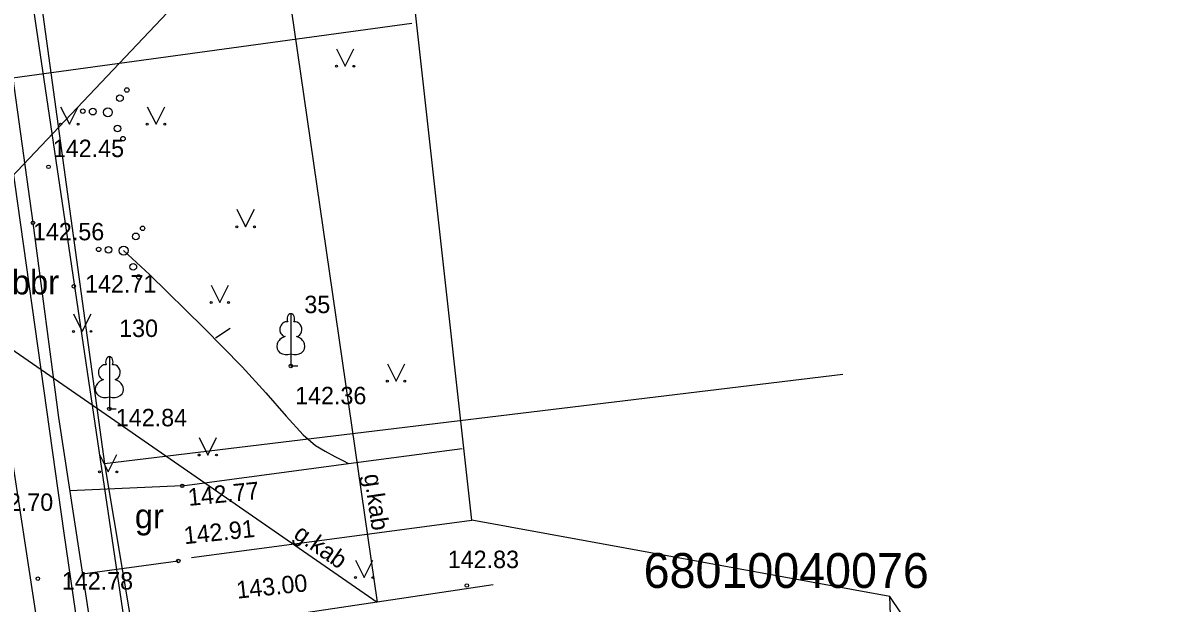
# Model space of a CAD drawing. Extents: x 728710 to 728960, y 272811 to 273475.
# Drawn here: x 728835.24 to 728867.91, y 273016.6 to 273033.26 of the extents above; entities that cross this region are included whole.
import ezdxf

# ---------------------------------------------------------------- set-up
doc = ezdxf.new("R2010")
doc.units = 0
for name, color, linetype in [('Level 3', 7, 'Continuous'), ('Level 30', 7, 'Continuous'), ('Level 4', 7, 'Continuous'), ('Level 48', 7, 'Continuous'), ('Level 56', 7, 'Continuous'), ('Level 57', 7, 'Continuous'), ('Level 58', 7, 'Continuous'), ('Level 6', 7, 'Continuous'), ('RAMI_UZMR_####_####_#', 7, 'Continuous'), ('RELJ_NOGA_####_####_#', 7, 'Continuous'), ('ROBZ_ELEM_####_####_#', 7, 'Continuous'), ('ROBZ_KADS_####_TKST_#', 7, 'Continuous'), ('ROBZ_UZMR_####_####_#', 7, 'Continuous'), ('SAKT_VADV_PKAB_TKST_#', 7, 'Continuous'), ('TERT_ELEM_####_####_#', 7, 'Continuous'), ('TERT_KONT_####_####_#', 7, 'Continuous')]:
    doc.layers.add(name, color=color, linetype=linetype)

msp = doc.modelspace()

# ---------------------------------------------------------------- linework, layer by layer
at = {"layer": 'Level 3'}
msp.add_line((728848.736, 273017.127), (728842.079, 273016.127), dxfattribs=at)
at = {"layer": 'Level 30'}
msp.add_lwpolyline([(728838.135, 273026.717), (728838.881, 273026.03), (728840.436, 273024.505), (728841.537, 273023.381), (728842.212, 273022.638), (728842.802, 273021.962), (728843.285, 273021.431), (728843.636, 273021.124), (728843.918, 273020.959), (728844.191, 273020.812), (728844.425, 273020.691), (728844.589, 273020.605)], dxfattribs=at)
at = {"layer": 'Level 4'}
for p, q in [((728843.115, 273032.795), (728846.401, 273033.246)), ((728834.947, 273031.673), (728843.115, 273032.795)), ((728845.021, 273020.663), (728847.851, 273021.041)), ((728839.817, 273019.968), (728845.021, 273020.663)), ((728839.817, 273019.968), (728836.589, 273019.822)), ((728845.481, 273018.628), (728848.126, 273018.981)), ((728840.084, 273017.907), (728845.481, 273018.628)), ((728836.954, 273017.436), (728839.703, 273017.811))]:
    msp.add_line(p, q, dxfattribs=at)
for points in [[(728845.654, 273100.85), (728832.719, 273098.413), (728826.071, 273097.316), (728825.017, 273097.001), (728824.765, 273096.832), (728824.532, 273096.455), (728824.532, 273096.455), (728826.161, 273084.877), (728827.437, 273076.575), (728829.749, 273059.3), (728831.728, 273043.761), (728834.021, 273027.538), (728834.782, 273021.709), (728836.279, 273011.943), (728839.357, 272993.501), (728839.499, 272992.383), (728841.21, 272978.381), (728843.301, 272966.86), (728843.797, 272965.94)], [(728845.919, 273099.374), (728832.98, 273096.936), (728826.409, 273095.852), (728826.143, 273095.772), (728827.647, 273085.083), (728828.941, 273076.709), (728831.314, 273059.418), (728833.202, 273044.226), (728835.526, 273027.512), (728836.266, 273021.924), (728837.76, 273012.18), (728840.331, 272994.327), (728840.331, 272994.327), (728840.331, 272994.327), (728842.687, 272979.229), (728844.615, 272968.066)], [(728860.318, 273011.281), (728860.116, 273016.786)]]:
    msp.add_lwpolyline(points, dxfattribs=at)
at = {"layer": 'Level 48'}
for centre in [(728835.98, 273029.123), (728835.533, 273027.513), (728836.704, 273025.693), (728842.933, 273023.406), (728837.725, 273022.174), (728839.817, 273019.968), (728839.703, 273017.811), (728835.673, 273017.302), (728847.982, 273017.104)]:
    msp.add_circle(centre, 0.05, dxfattribs=at)
at = {"layer": 'Level 6'}
msp.add_line((728840.77, 273024.214), (728841.188, 273024.489), dxfattribs=at)
at = {"layer": 'RAMI_UZMR_####_####_#'}
for points in [[(728862.157, 272893.095), (728861.3, 272900.225), (728860.555, 272913.018), (728859.353, 272922.664), (728857.836, 272933.151), (728857.298, 272939.138), (728865.025, 272943.82), (728867.908, 272945.567), (728865.999, 272958.94), (728863.367, 272971.714), (728860.682, 272977.116), (728851.003, 272976.08), (728851.179, 272982.093), (728851.003, 272989.484), (728862.411, 272996.126), (728865.099, 273006.046), (728863.87, 273011.218), (728860.116, 273016.786), (728848.126, 273018.981), (728842.745, 273067.512)], [(728842.48, 273036.82), (728822.849, 273016.092)], [(728842.48, 273036.82), (728845.408, 273016.627)], [(728822.045, 273032.801), (728845.408, 273016.627)]]:
    msp.add_lwpolyline(points, dxfattribs=at)
at = {"layer": 'ROBZ_ELEM_####_####_#'}
msp.add_lwpolyline([(728827.017, 273094.024), (728832.315, 273055.38), (728845.254, 272968.134)], dxfattribs=at)
at = {"layer": 'ROBZ_UZMR_####_####_#'}
for p, q in [((728832.202, 273059.745), (728837.586, 273020.598)), ((728858.776, 273023.162), (728837.586, 273020.598)), ((728837.586, 273020.598), (728842.238, 272993.006))]:
    msp.add_line(p, q, dxfattribs=at)
at = {"layer": 'TERT_ELEM_####_####_#'}
msp.add_lwpolyline([(728832.465, 273047.568), (728833.163, 273041.758), (728834, 273035.77), (728836.422, 273018.61), (728837.731, 273009.628), (728838.803, 273002.448), (728839.303, 272998.864)], dxfattribs=at)
at = {"layer": 'TERT_KONT_####_####_#'}
for p, q in [((728844.244, 273032.507), (728844.494, 273032.007)), ((728844.494, 273032.007), (728844.744, 273032.507)), ((728836.327, 273030.848), (728836.577, 273030.348)), ((728836.577, 273030.348), (728836.827, 273030.848)), ((728838.814, 273030.848), (728839.064, 273030.348)), ((728839.064, 273030.348), (728839.314, 273030.848)), ((728841.386, 273027.902), (728841.636, 273027.402)), ((728841.636, 273027.402), (728841.886, 273027.902)), ((728840.643, 273025.728), (728840.893, 273025.228)), ((728840.893, 273025.228), (728841.143, 273025.728)), ((728836.699, 273024.898), (728836.949, 273024.398)), ((728836.949, 273024.398), (728837.199, 273024.898)), ((728842.933, 273023.753), (728842.933, 273023.406)), ((728845.702, 273023.468), (728845.952, 273022.968)), ((728845.952, 273022.968), (728846.202, 273023.468)), ((728842.933, 273023.406), (728843.133, 273023.406)), ((728837.725, 273022.521), (728837.725, 273022.174)), ((728837.725, 273022.174), (728837.925, 273022.174)), ((728840.3, 273021.351), (728840.55, 273020.851)), ((728840.55, 273020.851), (728840.8, 273021.351)), ((728837.442, 273020.865), (728837.692, 273020.365)), ((728837.692, 273020.365), (728837.942, 273020.865)), ((728844.787, 273017.833), (728845.037, 273017.333)), ((728845.037, 273017.333), (728845.287, 273017.833))]:
    msp.add_line(p, q, dxfattribs=at)
for points in [[(728842.933, 273024.906), (728842.933, 273023.753)], [(728843.022, 273024.674), (728843.021, 273024.675)], [(728837.725, 273023.674), (728837.725, 273022.521)], [(728837.815, 273023.441), (728837.814, 273023.442)]]:
    msp.add_lwpolyline(points, dxfattribs=at)
for centre, radius in [((728844.244, 273032.007), 0.028), ((728844.744, 273032.007), 0.0263), ((728838.226, 273031.325), 0.064), ((728838.029, 273031.093), 0.096), ((728836.963, 273030.72), 0.064), ((728837.248, 273030.706), 0.096), ((728837.682, 273030.686), 0.128), ((728836.327, 273030.347), 0.028), ((728836.827, 273030.347), 0.0263), ((728837.958, 273030.219), 0.096), ((728838.813, 273030.347), 0.028), ((728839.313, 273030.347), 0.0263), ((728838.116, 273029.93), 0.064), ((728838.679, 273027.356), 0.064), ((728841.386, 273027.401), 0.028), ((728841.886, 273027.401), 0.0263), ((728838.483, 273027.125), 0.096), ((728837.417, 273026.751), 0.064), ((728837.701, 273026.738), 0.096), ((728838.135, 273026.717), 0.128), ((728838.412, 273026.25), 0.096), ((728838.569, 273025.961), 0.064), ((728840.643, 273025.227), 0.028), ((728841.143, 273025.227), 0.0263), ((728836.698, 273024.398), 0.028), ((728837.198, 273024.398), 0.0263), ((728845.701, 273022.968), 0.028), ((728846.201, 273022.968), 0.0263), ((728840.3, 273020.851), 0.028), ((728840.8, 273020.851), 0.0263), ((728837.442, 273020.365), 0.028), ((728837.942, 273020.365), 0.0263), ((728844.787, 273017.333), 0.028), ((728845.287, 273017.333), 0.0263)]:
    msp.add_circle(centre, radius, dxfattribs=at)
for centre, major_axis, ratio, start_param, end_param in [((728842.933, 273024.756), (0, -0.15), 0.707107, 3.14537, 5.287485), ((728842.932, 273024.756), (0, -0.15), 0.707107, 0.995701, 3.137816), ((728842.804, 273024.462), (-0.039, -0.212), 0.861323, 3.141593, 6.283185), ((728843.061, 273024.462), (0.039, -0.212), 0.861323, 0, 3.141593), ((728842.843, 273023.999), (0.307, 0.095), 0.814445, 1.570796, 4.752015), ((728843.022, 273023.999), (-0.307, 0.095), 0.814445, 1.531171, 4.712389), ((728837.597, 273023.229), (-0.039, -0.212), 0.861323, 3.141593, 6.283185), ((728837.725, 273023.524), (0, -0.15), 0.707107, 3.14537, 5.287485), ((728837.725, 273023.524), (0, -0.15), 0.707107, 0.995701, 3.137816), ((728837.853, 273023.229), (0.039, -0.212), 0.861323, 0, 3.141593), ((728837.635, 273022.767), (0.307, 0.095), 0.814445, 1.570796, 4.752015), ((728837.815, 273022.767), (-0.307, 0.095), 0.814445, 1.531171, 4.712389)]:
    msp.add_ellipse(centre, major_axis=major_axis, ratio=ratio, start_param=start_param, end_param=end_param, dxfattribs=at)

# ---------------------------------------------------------------- texts
at = {"layer": 'Level 56'}
msp.add_text(' 142.70', height=0.5, dxfattribs=at).set_placement((728833.883, 273019.247))
at = {"layer": 'Level 57'}
for s, p in [(' 142.45', (728835.916, 273029.401)), ('142.56', (728835.533, 273027.013)), (' 142.71', (728836.842, 273025.513)), (' 142.36', (728842.869, 273022.307)), (' 142.84', (728837.725, 273021.674)), (' 142.83', (728847.249, 273017.605)), (' 142.78', (728836.175, 273016.989))]:
    msp.add_text(s, height=0.5, dxfattribs=at).set_placement(p)
for s, rotation, p in [(' 142.77', 5.6516, (728839.82, 273019.37)), (' 142.91', 5.9346, (728839.702, 273018.271)), (' 143.00', 6.0798, (728841.211, 273016.707))]:
    msp.add_text(s, height=0.5, rotation=rotation, dxfattribs=at).set_placement(p)
at = {"layer": 'Level 58'}
for s, p in [('bbr', (728834.929, 273025.461)), ('gr', (728838.457, 273018.747))]:
    msp.add_text(s, height=0.7, dxfattribs=at).set_placement(p)
at = {"layer": 'RELJ_NOGA_####_####_#'}
for s, p in [('35', (728843.32, 273024.922)), ('130', (728838.006, 273024.238))]:
    msp.add_text(s, height=0.5, dxfattribs=at).set_placement(p)
at = {"layer": 'ROBZ_KADS_####_TKST_#'}
msp.add_text('68010040076', height=1, dxfattribs=at).set_placement((728853.057, 273017.036))
at = {"layer": 'SAKT_VADV_PKAB_TKST_#'}
for rotation, p in [(278.2496, (728845.03, 273020.277)), (325.3043, (728842.979, 273018.491))]:
    msp.add_text('g.kab', height=0.5, rotation=rotation, dxfattribs=at).set_placement(p)

doc.saveas('drawing.dxf')
